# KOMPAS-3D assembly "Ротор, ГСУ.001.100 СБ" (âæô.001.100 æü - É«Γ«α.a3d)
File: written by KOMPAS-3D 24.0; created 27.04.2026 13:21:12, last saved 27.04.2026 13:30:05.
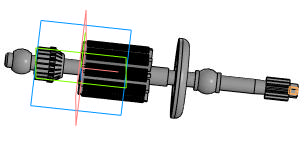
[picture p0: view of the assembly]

Document properties: Автор: User7; Полное имя файла: C:\Users\User7\Desktop\Двигатель мясорубки\ГСУ.001.100 СБ - Ротор.a3d

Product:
- Component [detail]: Звездочка  | designation ГСУ.001.101  | qty 1  | pos. 1  | Масса: 0.070368; Автор: User7; source file: ГСУ.001.101 - Звездочка.m3d
- Component [detail]: Вал ротора  | designation ГСУ.001.102  | qty 1  | pos. 2  | Масса: 0.060496; Автор: User7; source file: ГСУ.001.102 - Вал ротора.m3d
- Component [detail]: Шестеренка  | designation ГСУ.001.103  | qty 1  | pos. 3  | Масса: 0.004863; Автор: User7; source file: ГСУ.001.103 - Шестеренка.m3d
- Component [detail]: Пропеллер  | designation ГСУ.001.104  | qty 1  | pos. 4  | Масса: 0.033692; Автор: User7; source file: ГСУ.001.104 - Пропеллер.m3d
- Component [detail]: Коллектор  | designation ГСУ.001.105  | qty 1  | pos. 5  | Масса: 0.01991; Автор: User7; source file: ГСУ.001.105 - Коллектор.m3d
- Component [detail]: Шайба  | designation ГСУ.001.106  | qty 2  | pos. 6  | Масса: 0.000703; Автор: User7; source file: ГСУ.001.106 - Шайба.m3d
- Component [detail]: Втулка  | designation ГСУ.001.107  | qty 2  | pos. 7  | Масса: 0.00612; Автор: User7; source file: ГСУ.001.107 - Втулка.m3d
- Component [detail]: Пластина  | designation ГСУ.001.108  | qty 10  | pos. 8  | Масса: 0.00166; Автор: User7; source file: ГСУ.001.108 - Пластина.m3d
- Component [standard]: Гайка М4-6H ГОСТ 15523-70  | qty 1  | pos. 9  | Масса: 0.001183; Раздел спецификации: Стандартные изделия; Рассекать на разрезах: no
- Part/product: Ротор  | designation ГСУ.001.100 СБ
    Масса: 0.220757
    Форматы листов документа: A4
    source file: ГСУ.001.100 СБ - Ротор.spw

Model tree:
1. Массив по концентрической сетке:1  (with: Грань.Элемент выдавливания:1, Ребро.Элемент выдавливания:2, Грань.Элемент выдавливания:2, Ребро.Элемент выдавливания:6, Грань.Элемент выдавливания:6, Ребро.Элемент вращения:1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)  (labels: Грань.Элемент выдавливания:1.Экземпляр ( 98, 1 ); Грань.Элемент выдавливания:1.Экземпляр ( 110, 1 ))  (10 pattern instances)
     Шаг 2 = 360; Расстояние = 38.2; Расстояние = 19; Расстояние = 10; Расстояние = 1.95; Расстояние = -4; Расстояние = 2.5

Referenced files in C:\Users\User7\Desktop\Двигатель мясорубки\: ГСУ.001.101 - Звездочка.m3d, ГСУ.001.102 - Вал ротора.m3d, ГСУ.001.103 - Шестеренка.m3d, ГСУ.001.104 - Пропеллер.m3d, ГСУ.001.105 - Коллектор.m3d, ГСУ.001.106 - Шайба.m3d, ГСУ.001.107 - Втулка.m3d, ГСУ.001.108 - Пластина.m3d
Referenced files in C:\Program Files\ASCON\KOMPAS-3D v21\Libs\PARTLib\DATA\vault\Methods\Kompas\3D\: PLib_Nut_OST92_900.m3d
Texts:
  ГСУ.001.101
  ГСУ.001.102
  ГСУ.001.103
  ГСУ.001.104
  ГСУ.001.105
  ГСУ.001.106
  ГСУ.001.107
  ГСУ.001.108
  Крепежное изделие ГОСТ
  Программные изделия  и базы данных
  ГСУ.001.100 СБ
  ГСУ.001.101 Звездочка
  ГСУ.001.102 Вал ротора
  ГСУ.001.103 Шестеренка
  ГСУ.001.104 Пропеллер
  ГСУ.001.105 Коллектор
  ГСУ.001.106 Шайба (1)
  ГСУ.001.106 Шайба (2)
  ГСУ.001.107 Втулка (1)
  ГСУ.001.107 Втулка (2)
  ГСУ.001.108 Пластина (1)
  ГСУ.001.108 Пластина (2)
  ГСУ.001.108 Пластина (3)
  ГСУ.001.108 Пластина (4)
  ГСУ.001.108 Пластина (5)
  ГСУ.001.108 Пластина (6)
  ГСУ.001.108 Пластина (7)
  ГСУ.001.108 Пластина (8)
  ГСУ.001.108 Пластина (9)
  ГСУ.001.108 Пластина (10)
  bcut1
  hole1
  hcut1
  hole2
  cut1
  Plane. Начало координат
